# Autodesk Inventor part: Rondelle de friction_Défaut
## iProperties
Shininess: 64.0
Length Units: 11269
Angle Units: 11279
Time Units: 11290
Mass Units: 11283
Length Display Precision: 3
Angle Display Precision: 2
Compacted: True
Part Number: Rondelle de friction_Défaut
Document SubType Name: Modeling
Created: 2006-01
Material: Par défaut
Designer: riri
Density: 0.0
Volumn: 0.0
Area: 0.0
PropertySet Name: Model Information
Control State: 0
Master: False
Checked Out: False
Author: riri
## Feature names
1. Base1
